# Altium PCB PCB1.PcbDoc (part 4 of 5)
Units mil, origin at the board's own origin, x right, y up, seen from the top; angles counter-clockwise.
Board outline 4463 x 4481 mil, 2 copper layers (Top Layer, Bottom Layer); 0 components, 111 nets, 310 pads, 0 vias.
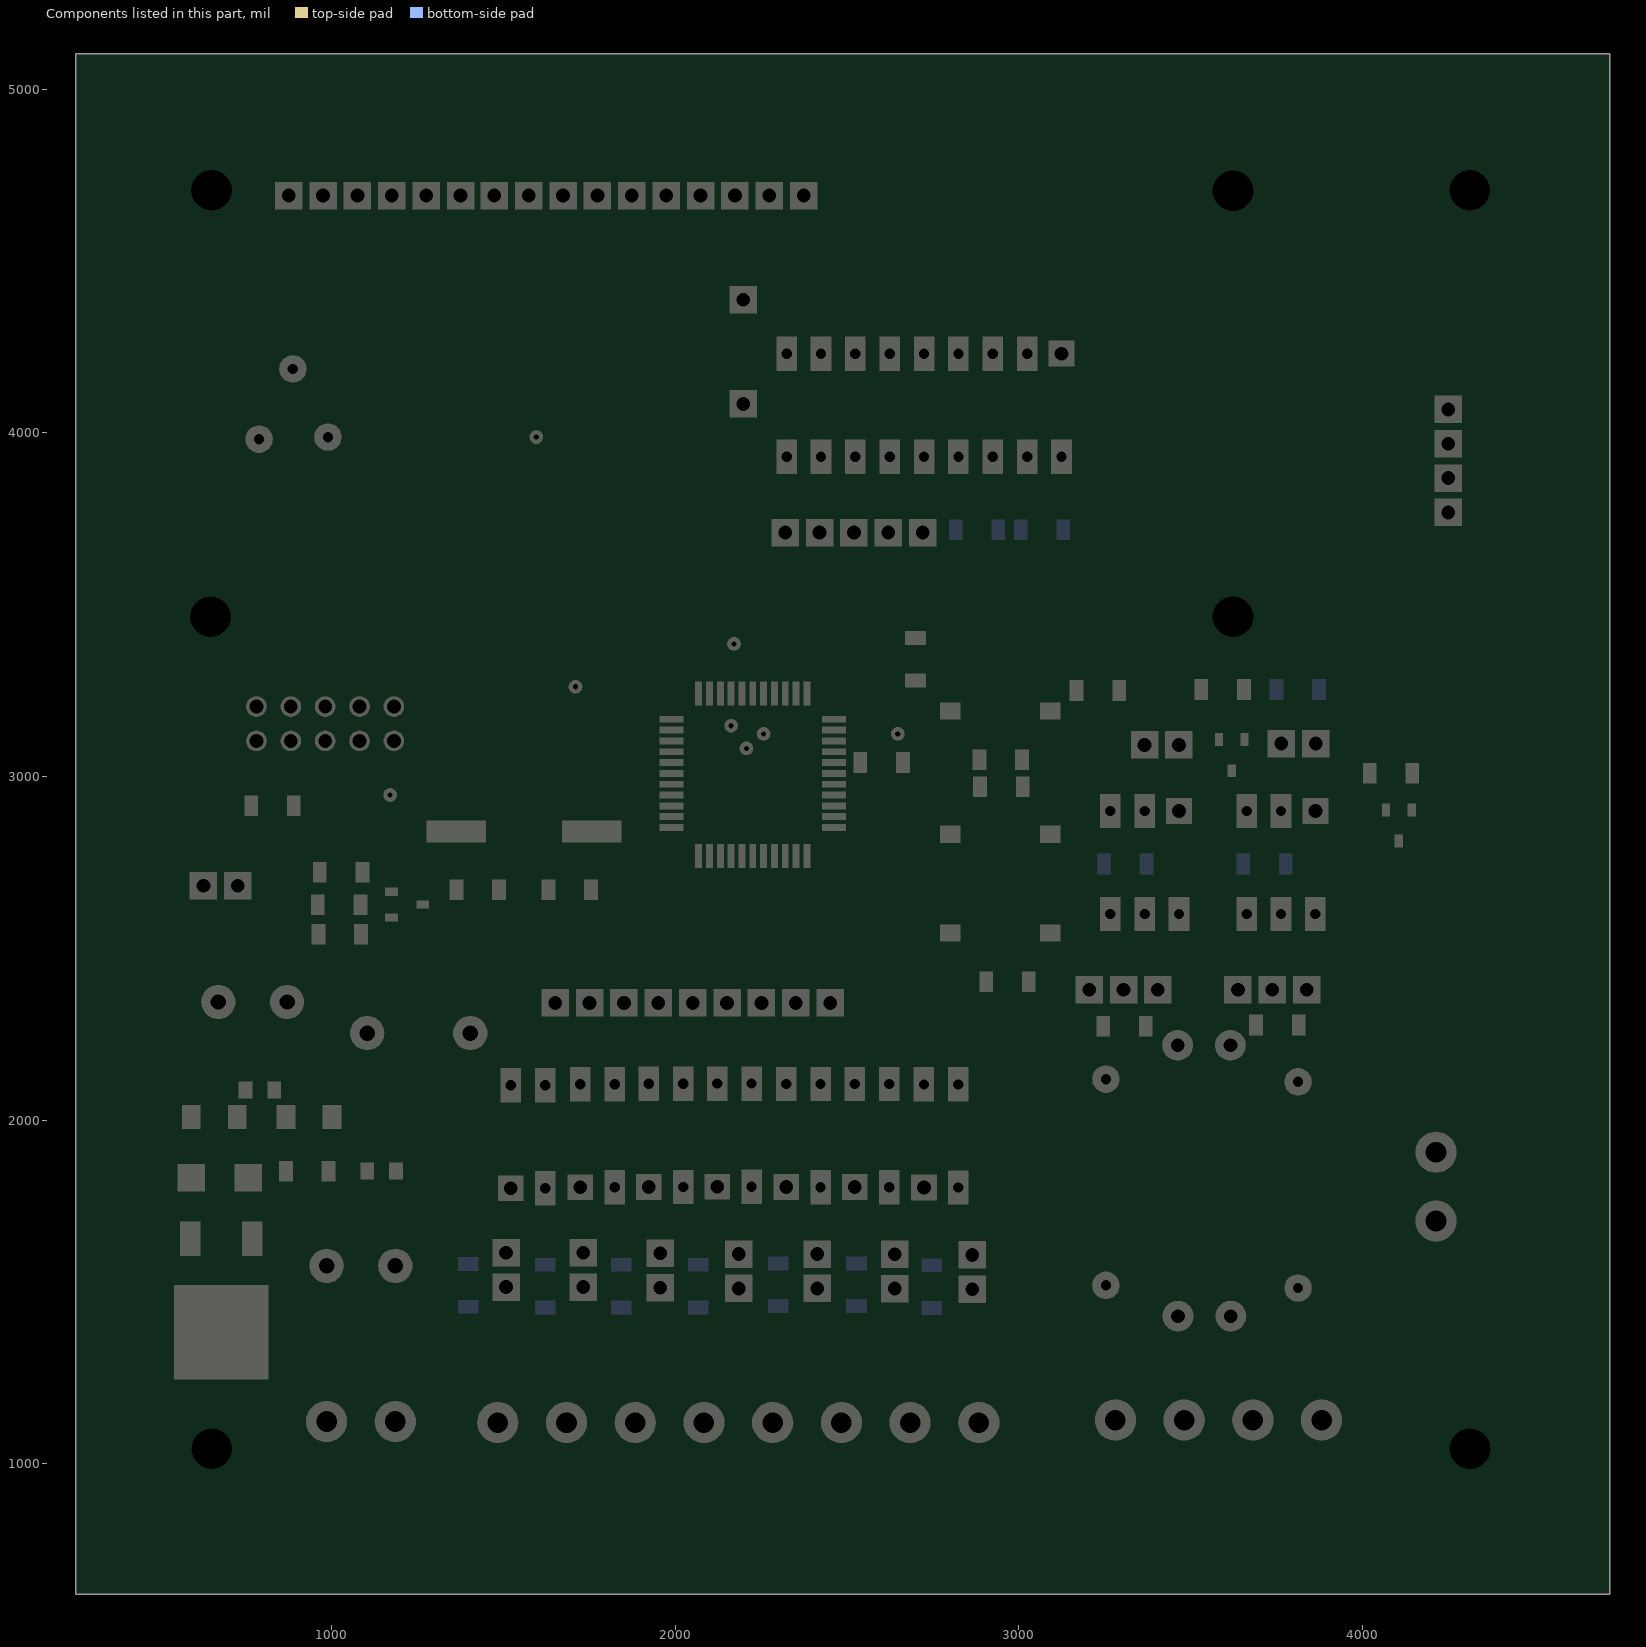
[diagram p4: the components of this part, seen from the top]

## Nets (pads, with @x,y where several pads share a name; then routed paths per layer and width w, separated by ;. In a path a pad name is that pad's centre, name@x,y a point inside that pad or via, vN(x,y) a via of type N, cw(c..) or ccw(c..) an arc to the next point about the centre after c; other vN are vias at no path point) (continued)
copper on no net: (continued)
  Bottom Layer w15: 514.04,931.9 4450.24,931.9 ; 514.04,956.9 588.64,956.9 ; 514.04,981.9 563.64,981.9 ; 514.04,1006.9 546.04,1006.9 ; 514.04,1031.9 546.04,1031.9 ; 514.04,1056.9 546.04,1056.9 ; 514.04,1081.9 546.04,1081.9 ; 514.04,1106.9 565.34,1106.9 ; 514.04,1131.9 590.34,1131.9 ; 514.04,1156.9 898.64,1156.9 ; 514.04,1181.9 921.24,1181.9 ; 514.04,1206.9 943.64,1206.9 ; 514.04,1231.9 943.64,1231.9 ; 514.04,1256.9 943.64,1256.9 ; 514.04,1281.9 943.64,1281.9 ; 514.04,1306.9 943.64,1306.9 ; 514.04,1331.9 943.64,1331.9 ; 514.04,1356.9 943.64,1356.9 ; 514.04,1381.9 943.64,1381.9 ; 514.04,1406.9 943.64,1406.9 ; 514.04,1431.9 943.64,1431.9 ; 514.04,1456.9 943.64,1456.9 ; 514.04,1481.9 943.64,1481.9 ; 514.04,1506.9 943.64,1506.9 ; 514.04,1531.9 920.44,1531.9 ; 514.04,1556.9 908.64,1556.9 ; 514.04,1581.9 908.64,1581.9 ; 514.04,1606.9 908.64,1606.9 ; 514.04,1631.9 932.64,1631.9 ; 514.04,1656.9 1363.34,1656.9 ; 514.04,1681.9 1363.34,1681.9 ; 514.04,1706.9 1363.34,1706.9 ; 514.04,1731.9 1363.34,1731.9 ; 514.04,1756.9 1363.34,1756.9 ; 514.04,1781.9 1367.54,1781.9 ; 514.04,1806.9 1392.54,1806.9 ; 514.04,1831.9 1417.54,1831.9 ; 514.04,1856.9 1457.34,1856.9 ; 514.04,1881.9 1766.84,1881.9 ; 514.04,1906.9 2934.54,1906.9 ; 514.04,1931.9 2934.54,1931.9 ; 514.04,1956.9 2934.54,1956.9 ; 514.04,1981.9 1626.64,1981.9 ; 514.04,2006.9 1601.64,2006.9 ; 514.04,2031.9 1464.84,2031.9 ; 514.04,2056.9 1464.84,2056.9 ; 514.04,2081.9 1464.84,2081.9 ; 514.04,2106.9 1464.84,2106.9 ; 514.04,2131.9 1464.84,2131.9 ; 514.04,2156.9 1464.84,2156.9 ; 514.04,2181.9 1065.74,2181.9 ; 514.04,2206.9 1040.74,2206.9 ; 514.04,2231.9 1026.74,2231.9 ; 514.04,2256.9 1026.74,2256.9 ; 514.04,2281.9 623.24,2281.9 ; 514.04,2306.9 598.24,2306.9 ; 514.04,2331.9 593.64,2331.9 ; 514.04,2356.9 593.64,2356.9 ; 514.04,2381.9 581.44,2381.9 ; 514.04,2406.9 581.44,2406.9 ; 514.04,2431.9 581.44,2431.9 ; 514.04,2456.9 581.44,2456.9 ; 514.04,2481.9 581.44,2481.9 ; 514.04,2506.9 581.44,2506.9 ; 514.04,2531.9 581.44,2531.9 ; 514.04,2556.9 581.44,2556.9 ; 514.04,2581.9 581.44,2581.9 ; 514.04,2606.9 581.44,2606.9 ; 514.04,2631.9 560.34,2631.9 ; 514.04,2656.9 560.34,2656.9 ; 514.04,2681.9 560.34,2681.9 ; 514.04,2706.9 560.34,2706.9 ; 514.04,2731.9 560.34,2731.9 ; 514.04,2756.9 592.84,2756.9 ; 514.04,2781.9 592.84,2781.9 ; 514.04,2806.9 592.84,2806.9 ; 514.04,2831.9 592.84,2831.9 ; 514.04,2856.9 592.84,2856.9 ; 514.04,2881.9 592.84,2881.9 ; 514.04,2906.9 592.84,2906.9 ; 514.04,2931.9 592.84,2931.9 ; 514.04,2956.9 592.84,2956.9 ; 514.04,2981.9 592.84,2981.9 ; 514.04,3006.9 592.84,3006.9 ; 514.04,3031.9 592.84,3031.9 ; 514.04,3056.9 592.84,3056.9 ; 514.04,3081.9 592.84,3081.9 ; 514.04,3106.9 592.84,3106.9 ; 514.04,3131.9 592.84,3131.9 ; 514.04,3156.9 616.24,3156.9 ; 514.04,3181.9 641.24,3181.9 ; 514.04,3206.9 724.74,3206.9 ; 514.04,3231.9 729.54,3231.9 ; 514.04,3256.9 754.54,3256.9 ; 514.04,3281.9 1096.44,3281.9 ; 514.04,3306.9 1096.44,3306.9 ; 514.04,3331.9 1096.44,3331.9 ; 514.04,3356.9 1096.44,3356.9 ; 514.04,3381.9 580.54,3381.9 ; 514.04,3406.9 555.54,3406.9 ; 514.04,3431.9 542.14,3431.9 ; 514.04,3456.9 542.14,3456.9 ; 514.04,3481.9 542.14,3481.9 ; 514.04,3506.9 542.14,3506.9 ; 514.04,3531.9 565.74,3531.9 ; 514.04,3556.9 590.74,3556.9 ; 514.04,3581.9 1241.64,3581.9 ; 514.04,3606.9 1241.64,3606.9 ; 514.04,3631.9 1241.64,3631.9 ; 514.04,3656.9 1241.64,3656.9 ; 514.04,3681.9 1241.64,3681.9 ; 514.04,3706.9 1241.64,3706.9 ; 514.04,3731.9 1241.64,3731.9 ; 514.04,3756.9 1241.64,3756.9 ; 514.04,3781.9 1241.64,3781.9 ; 514.04,3806.9 1241.64,3806.9 ; 514.04,3831.9 1241.64,3831.9 ; 514.04,3856.9 1241.64,3856.9 ; 514.04,3881.9 1241.64,3881.9 ; 514.04,3906.9 1241.64,3906.9 ; 514.04,3931.9 743.54,3931.9 ; 514.04,3956.9 722.14,3956.9 ; 514.04,3981.9 722.14,3981.9 ; 514.04,4006.9 722.14,4006.9 ; 514.04,4031.9 744.84,4031.9 ; 514.04,4056.9 754.64,4056.9 ; 514.04,4081.9 754.64,4081.9 ; 514.04,4106.9 754.64,4106.9 ; 514.04,4131.9 754.64,4131.9 ; 514.04,4156.9 754.64,4156.9 ; 514.04,4181.9 754.64,4181.9 ; 514.04,4206.9 754.64,4206.9 ; 514.04,4231.9 754.64,4231.9 ; 514.04,4256.9 754.64,4256.9 ; 514.04,4281.9 754.64,4281.9 ; 514.04,4306.9 754.64,4306.9 ; 514.04,4331.9 754.64,4331.9 ; 514.04,4356.9 754.64,4356.9 ; 514.04,4381.9 754.64,4381.9 ; 514.04,4406.9 754.64,4406.9 ; 514.04,4431.9 754.64,4431.9 ; 514.04,4456.9 759.14,4456.9 ; 514.04,4481.9 784.14,4481.9 ; 514.04,4506.9 809.14,4506.9 ; 514.04,4531.9 834.14,4531.9 ; 514.04,4556.9 836.94,4556.9 ; 514.04,4581.9 836.94,4581.9 ; 514.04,4606.9 600.04,4606.9 ; 514.04,4631.9 575.04,4631.9 ; 514.04,4656.9 550.04,4656.9 ; 514.04,4681.9 545.24,4681.9 ; 514.04,4706.9 545.24,4706.9 ; 514.04,4731.9 545.24,4731.9 ; 514.04,4756.9 552.44,4756.9 ; 514.04,4781.9 577.44,4781.9 ; 514.04,4806.9 602.44,4806.9 ; 514.04,4831.9 4450.24,4831.9 ; 539.04,906.9 539.04,4841.9 ; 564.04,906.9 564.04,981.5 ; 564.04,1105.6 564.04,2614.6 ; 564.04,2749.6 564.04,3398.4 ; 564.04,3530.2 564.04,4642.8 ; 564.04,4768.5 564.04,4841.9 ; 589.04,906.9 589.04,956.5 ; 589.04,1130.6 589.04,2365.6 ; 589.04,2749.6 589.04,3373.4 ; 589.04,3555.2 589.04,4617.8 ; 589.04,4793.5 589.04,4841.9 ; 614.04,906.9 614.04,937.3 ; 614.04,1149.8 614.04,2291.1 ; 614.04,3154.7 614.04,3358.1 ; 614.04,3570.6 614.04,4599.4 ; 614.04,4811.9 614.04,4841.9 ; 639.04,906.9 639.04,937.3 ; 639.04,1149.8 639.04,2266.1 ; 639.04,3179.7 639.04,3358.1 ; 639.04,3570.6 639.04,4599.4 ; 639.04,4811.9 639.04,4841.9 ; 662.84,2756.9 3172.74,2756.9 ; 662.84,2781.9 3200.34,2781.9 ; 662.84,2806.9 4450.24,2806.9 ; 662.84,2831.9 3208.84,2831.9 ; 662.84,2856.9 3208.84,2856.9 ; 662.84,2881.9 3208.84,2881.9 ; 662.84,2906.9 1142.94,2906.9 ; 662.84,2931.9 1123.64,2931.9 ; 662.84,2956.9 1123.64,2956.9 ; 662.84,2981.9 1140.14,2981.9 ; 662.84,3006.9 1182.74,3006.9 ; 662.84,3031.9 1207.74,3031.9 ; 662.84,3056.9 747.34,3056.9 ; 662.84,3081.9 724.74,3081.9 ; 664.04,906.9 664.04,937.3 ; 664.04,1149.8 664.04,2266.1 ; 664.04,2749.6 664.04,3105.7 ; 664.04,3189.5 664.04,3358.1 ; 664.04,3570.6 664.04,4599.4 ; 664.04,4811.9 664.04,4841.9 ; 665.24,3106.9 724.74,3106.9 ; 666.44,2431.9 3137.44,2431.9 ; 666.44,2456.9 3236.54,2456.9 ; 666.44,2481.9 3211.54,2481.9 ; 666.44,2506.9 3186.54,2506.9 ; 666.44,2531.9 3161.54,2531.9 ; 666.44,2556.9 3155.74,2556.9 ; 666.44,2581.9 3155.74,2581.9 ; 666.44,2606.9 3155.74,2606.9 ; 689.04,906.9 689.04,937.3 ; 689.04,1149.8 689.04,2266.1 ; 689.04,2421.1 689.04,2614.6 ; 689.04,2749.6 689.04,3119.5 ; 689.04,3189.5 689.04,3358.1 ; 689.04,3570.6 689.04,4599.4 ; 689.04,4811.9 689.04,4841.9 ; 700.54,4806.9 3575.94,4806.9 ; 702.94,4606.9 836.94,4606.9 ; 706.04,3556.9 1241.64,3556.9 ; 714.04,906.9 714.04,955.1 ; 714.04,1132.1 714.04,2276.9 ; 714.04,2410.3 714.04,2614.6 ; 714.04,2749.6 714.04,3119.5 ; 714.04,3189.5 714.04,3379.8 ; 714.04,3548.8 714.04,4618 ; 714.04,4793.3 714.04,4841.9 ; 714.24,1131.9 898.64,1131.9 ; 715.94,956.9 986.34,956.9 ; 716.14,3381.9 1120.04,3381.9 ; 717.44,2406.9 824.84,2406.9 ; 719.04,2281.9 823.24,2281.9 ; 725.54,4781.9 863.34,4781.9 ; 727.94,4631.9 808.44,4631.9 ; 731.04,3531.9 1241.64,3531.9 ; 739.04,906.9 739.04,980.1 ; 739.04,1107.1 739.04,2301.9 ; 739.04,2385.3 739.04,2614.6 ; 739.04,2749.6 739.04,3065.1 ; 739.04,3241.4 739.04,3404.8 ; 739.04,3523.8 739.04,3936.4 ; 739.04,4026.1 739.04,4643 ; 739.04,4768.3 739.04,4841.9 ; 739.24,1106.9 898.64,1106.9 ; 740.94,981.9 961.34,981.9 ; 741.14,3406.9 1145.04,3406.9 ; 742.44,2381.9 799.84,2381.9 ; 744.04,2306.9 798.24,2306.9 ; 748.64,2331.9 793.64,2331.9 ; 748.64,2356.9 793.64,2356.9 ; 750.54,4756.9 808.44,4756.9 ; 752.94,4656.9 808.44,4656.9 ; 754.54,3431.9 1170.04,3431.9 ; 754.54,3456.9 1195.04,3456.9 ; 754.54,3481.9 1220.04,3481.9 ; 754.54,3506.9 1241.64,3506.9 ; 757.74,4681.9 808.44,4681.9 ; 757.74,4706.9 808.44,4706.9 ; 757.74,4731.9 808.44,4731.9 ; 758.54,1006.9 942.44,1006.9 ; 758.54,1031.9 942.44,1031.9 ; 758.54,1056.9 928.54,1056.9 ; 758.54,1081.9 903.54,1081.9 ; 764.04,906.9 764.04,2614.6 ; 764.04,2749.6 764.04,3045.8 ; 764.04,3260.8 764.04,3913.7 ; 764.04,4461.8 764.04,4841.9 ; 789.04,906.9 789.04,2614.6 ; 789.04,2749.6 789.04,3045.8 ; 789.04,3260.8 789.04,3913.7 ; 789.04,4486.8 789.04,4841.9 ; 795.34,2631.9 3155.74,2631.9 ; 795.34,2656.9 3155.74,2656.9 ; 795.34,2681.9 3155.74,2681.9 ; 795.34,2706.9 3155.74,2706.9 ; 795.34,2731.9 3155.74,2731.9 ; 809.94,3256.9 854.44,3256.9 ; 814.04,906.9 814.04,2291.1 ; 814.04,2396.1 814.04,3053.8 ; 814.04,3252.7 814.04,3913.7 ; 814.04,4511.8 814.04,4622.4 ; 814.04,4757.4 814.04,4841.9 ; 817.14,3056.9 847.24,3056.9 ; 835.84,3931.9 949.94,3931.9 ; 839.04,906.9 839.04,2266.1 ; 839.04,3065.1 839.04,2421.1 ; 839.04,3241.5 839.04,3935.1 ; 839.04,4757.4 839.04,4841.9 ; 857.14,3956.9 924.94,3956.9 ; 857.14,3981.9 922.54,3981.9 ; 857.14,4006.9 920.84,4006.9 ; 864.04,906.9 864.04,2266.1 ; 864.04,2421.1 864.04,3045.8 ; 864.04,3260.8 864.04,4009.2 ; 864.04,4782.6 864.04,4841.9 ; 889.04,906.9 889.04,2266.1 ; 889.04,2421.1 889.04,3045.8 ; 889.04,3260.8 889.04,4009.2 ; 889.04,4803.7 889.04,4841.9 ; 909.94,3256.9 954.44,3256.9 ; 914.04,906.9 914.04,1071.4 ; 914.04,1174.7 914.04,1538.3 ; 914.04,1613.3 914.04,2276.9 ; 914.04,2410.3 914.04,3053.8 ; 914.04,3252.7 914.04,4009.2 ; 914.04,4803.7 914.04,4841.9 ; 917.14,3056.9 947.24,3056.9 ; 917.44,2406.9 1583.94,2406.9 ; 919.04,2281.9 1026.74,2281.9 ; 939.04,906.9 939.04,1046.4 ; 939.04,1199.7 939.04,1513.3 ; 939.04,1638.3 939.04,2301.9 ; 939.04,2385.3 939.04,3065.1 ; 939.04,3241.5 939.04,3942.7 ; 939.04,4803.7 939.04,4841.9 ; 942.44,2381.9 1583.94,2381.9 ; 944.04,2306.9 1048.54,2306.9 ; 948.64,2331.9 1583.94,2331.9 ; 948.64,2356.9 1583.94,2356.9 ; 964.04,906.9 964.04,979.2 ; 964.04,1653.3 964.04,3045.8 ; 964.04,3260.8 964.04,3919.7 ; 964.04,4803.7 964.04,4841.9 ; 989.04,906.9 989.04,955 ; 989.04,1653.3 989.04,3045.8 ; 989.04,3260.8 989.04,3919.7 ; 989.04,4803.7 989.04,4841.9 ; 1009.94,3256.9 1054.44,3256.9 ; 1014.04,906.9 1014.04,955 ; 1014.04,1653.3 1014.04,3053.8 ; 1014.04,3252.7 1014.04,3919.7 ; 1014.04,4803.7 1014.04,4841.9 ; 1017.14,3056.9 1047.24,3056.9 ; 1028.64,1206.9 1143.64,1206.9 ; 1028.64,1231.9 1143.64,1231.9 ; 1028.64,1256.9 1143.64,1256.9 ; 1028.64,1281.9 1143.64,1281.9 ; 1028.64,1306.9 1143.64,1306.9 ; 1028.64,1331.9 1143.64,1331.9 ; 1028.64,1356.9 1143.64,1356.9 ; 1028.64,1381.9 1143.64,1381.9 ; 1028.64,1406.9 1143.64,1406.9 ; 1028.64,1431.9 1143.64,1431.9 ; 1028.64,1456.9 1143.64,1456.9 ; 1028.64,1481.9 1143.64,1481.9 ; 1028.64,1506.9 1143.64,1506.9 ; 1030.24,3931.9 1241.64,3931.9 ; 1039.04,906.9 1039.04,955 ; 1039.04,1040 1039.04,1052.3 ; 1039.04,1193.9 1039.04,1519.1 ; 1039.04,1632.5 1039.04,2208.6 ; 1039.04,2297.4 1039.04,3065.1 ; 1039.04,3241.5 1039.04,3940.7 ; 1039.04,4803.7 1039.04,4841.9 ; 1039.64,1631.9 1132.64,1631.9 ; 1043.74,1056.9 1128.54,1056.9 ; 1051.04,1181.9 1121.24,1181.9 ; 1051.84,1531.9 1120.44,1531.9 ; 1063.64,1556.9 1108.64,1556.9 ; 1063.64,1581.9 1108.64,1581.9 ; 1063.64,1606.9 1108.64,1606.9 ; 1064.04,906.9 1064.04,955 ; 1064.04,1040 1064.04,1077.3 ; 1064.04,1168.9 1064.04,2183.6 ; 1064.04,2322.4 1064.04,3045.8 ; 1064.04,3260.8 1064.04,3952.2 ; 1064.04,4803.7 1064.04,4841.9 ; 1068.74,1081.9 1103.54,1081.9 ; 1073.64,1106.9 1098.64,1106.9 ; 1073.64,1131.9 1098.64,1131.9 ; 1073.64,1156.9 1098.64,1156.9 ; 1089.04,906.9 1089.04,955 ; 1089.04,1040 1089.04,2175.5 ; 1089.04,2330.5 1089.04,3045.8 ; 1089.04,3260.8 1089.04,3952.2 ; 1089.04,4803.7 1089.04,4841.9 ; 1114.04,906.9 1114.04,955 ; 1114.04,1040 1114.04,1071.4 ; 1114.04,1174.7 1114.04,1538.3 ; 1114.04,1613.3 1114.04,2175.5 ; 1114.04,2330.5 1114.04,3053.8 ; 1114.04,3375.9 1114.04,3952.2 ; 1114.04,4803.7 1114.04,4841.9 ; 1117.14,3056.9 1147.24,3056.9 ; 1139.04,906.9 1139.04,955 ; 1139.04,1040 1139.04,1046.4 ; 1139.04,1199.7 1139.04,1513.3 ; 1139.04,1638.3 1139.04,2178.2 ; 1139.04,2327.8 1139.04,2910.7 ; 1139.04,2980.8 1139.04,3065.1 ; 1139.04,3400.9 1139.04,3952.2 ; 1139.04,4803.7 1139.04,4841.9 ; 1142.74,2181.9 1365.74,2181.9 ; 1159.94,2306.9 1348.54,2306.9 ; 1164.04,906.9 1164.04,955 ; 1164.04,1653.3 1164.04,2203.2 ; 1164.04,2302.8 1164.04,2898.3 ; 1164.04,2993.3 1164.04,3045.8 ; 1164.04,3425.9 1164.04,3952.2 ; 1164.04,4803.7 1164.04,4841.9 ; 1167.74,2206.9 1340.74,2206.9 ; 1181.74,2231.9 1326.74,2231.9 ; 1181.74,2256.9 1326.74,2256.9 ; 1181.74,2281.9 1326.74,2281.9 ; 1189.04,906.9 1189.04,955 ; 1189.04,1653.3 1189.04,2898.3 ; 1189.04,3013.2 1189.04,3045.8 ; 1189.04,3450.9 1189.04,3952.2 ; 1189.04,4803.7 1189.04,4841.9 ; 1199.44,2906.9 3208.84,2906.9 ; 1214.04,906.9 1214.04,955 ; 1214.04,1653.3 1214.04,2921.5 ; 1214.04,3035.9 1214.04,3053.8 ; 1214.04,3152.7 1214.04,3153.8 ; 1214.04,3475.9 1214.04,3952.2 ; 1214.04,4803.7 1214.04,4841.9 ; 1217.14,3056.9 1539.84,3056.9 ; 1217.14,3156.9 1639.84,3156.9 ; 1217.14,3256.9 1663.04,3256.9 ; 1217.14,3281.9 1664.44,3281.9 ; 1218.64,2931.9 3208.84,2931.9 ; 1222.74,3306.9 1689.44,3306.9 ; 1228.64,1206.9 1447.44,1206.9 ; 1228.64,1231.9 1522.74,1231.9 ; 1228.64,1256.9 1497.74,1256.9 ; 1228.64,1281.9 1472.74,1281.9 ; 1228.64,1306.9 1447.74,1306.9 ; 1228.64,1331.9 1422.74,1331.9 ; 1228.64,1356.9 1397.74,1356.9 ; 1228.64,1381.9 1372.74,1381.9 ; 1228.64,1406.9 1364.94,1406.9 ; 1228.64,1431.9 1340.84,1431.9 ; 1228.64,1456.9 1340.84,1456.9 ; 1228.64,1481.9 1230.54,1481.9 ; 1231.74,2956.9 3208.84,2956.9 ; 1234.84,3231.9 1672.24,3231.9 ; 1234.94,3131.9 1614.84,3131.9 ; 1239.04,906.9 1239.04,955 ; 1239.04,1040 1239.04,1052.3 ; 1239.04,1193.9 1239.04,1479 ; 1239.04,1632.5 1239.04,2964.2 ; 1239.04,3035.9 1239.04,3078.8 ; 1239.04,3127.7 1239.04,3178.8 ; 1239.04,3227.7 1239.04,3316.3 ; 1239.04,3500.9 1239.04,3952.2 ; 1239.04,4803.7 1239.04,4841.9 ; 1239.64,1631.9 1363.34,1631.9 ; 1239.64,3081.9 1564.84,3081.9 ; 1239.64,3106.9 1589.84,3106.9 ; 1239.64,3181.9 1664.84,3181.9 ; 1239.64,3206.9 2819.64,3206.9 ; 1243.74,1056.9 1423.44,1056.9 ; 1251.04,1181.9 1422.44,1181.9 ; 1263.64,1556.9 1340.84,1556.9 ; 1263.64,1581.9 1340.84,1581.9 ; 1263.64,1606.9 1340.84,1606.9 ; 1264.04,906.9 1264.04,955 ; 1264.04,1040 1264.04,1077.3 ; 1264.04,1168.9 1264.04,1479 ; 1264.04,1549 1264.04,2965.9 ; 1264.04,3035.9 1264.04,3316.3 ; 1264.04,4803.7 1264.04,4841.9 ; 1268.74,1081.9 1398.44,1081.9 ; 1273.64,1106.9 1396.64,1106.9 ; 1273.64,1131.9 1396.64,1131.9 ; 1273.64,1156.9 1397.44,1156.9 ; 1289.04,906.9 1289.04,955 ; 1289.04,1040 1289.04,1479 ; 1289.04,1549 1289.04,2965.9 ; 1289.04,3035.9 1289.04,3316.3 ; 1289.04,4783 1289.04,4841.9 ; 1290.14,4781.9 3550.94,4781.9 ; 1314.04,906.9 1314.04,955 ; 1314.04,1040 1314.04,1479 ; 1314.04,1549 1314.04,2965.9 ; 1314.04,3035.9 1314.04,3316.3 ; 1314.04,4757.4 1314.04,4841.9 ; 1339.04,906.9 1339.04,955 ; 1339.04,1040 1339.04,1479 ; 1339.04,1549 1339.04,2208.6 ; 1339.04,2297.4 1339.04,2965.9 ; 1339.04,3035.9 1339.04,3316.3 ; 1339.04,4757.4 1339.04,4841.9 ; 1364.04,906.9 1364.04,955 ; 1364.04,1040 1364.04,1409.5 ; 1364.04,1778.4 1364.04,2183.6 ; 1364.04,2322.4 1364.04,2965.9 ; 1364.04,3035.9 1364.04,3316.3 ; 1364.04,4757.4 1364.04,4841.9 ; 1389.04,906.9 1389.04,955 ; 1389.04,1040 1389.04,1365.6 ; 1389.04,1803.4 1389.04,2175.5 ; 1389.04,2330.5 1389.04,2965.9 ; 1389.04,3035.9 1389.04,3316.3 ; 1389.04,4757.4 1389.04,4841.9 ; 1414.04,906.9 1414.04,955 ; 1414.04,1040 1414.04,1066.3 ; 1414.04,1173.6 1414.04,1340.6 ; 1414.04,1828.4 1414.04,2175.5 ; 1414.04,2330.5 1414.04,2965.9 ; 1414.04,3035.9 1414.04,3316.3 ; 1414.04,4757.4 1414.04,4841.9 ; 1439.04,906.9 1439.04,955 ; 1439.04,1198.6 1439.04,1315.6 ; 1439.04,1836.4 1439.04,2178.2 ; 1439.04,2327.8 1439.04,2965.9 ; 1439.04,3035.9 1439.04,3316.3 ; 1439.04,4757.4 1439.04,4841.9 ; 1442.74,2181.9 1489.34,2181.9 ; 1446.74,1406.9 1587.74,1406.9 ; 1455.84,1431.9 1565.24,1431.9 ; 1459.94,2306.9 1583.94,2306.9 ; 1463.94,956.9 4249.54,956.9 ; 1464.04,906.9 1464.04,957.1 ; 1464.04,1207.4 1464.04,1290.6 ; 1464.04,1389.6 1464.04,1446.5 ; 1464.04,1866.4 1464.04,2203.2 ; 1464.04,2302.8 1464.04,2965.9 ; 1464.04,3035.9 1464.04,3316.3 ; 1464.04,4757.4 1464.04,4841.9 ; 1467.74,2206.9 1489.34,2206.9 ; 1471.74,1381.9 1587.74,1381.9 ; 1481.74,2231.9 1489.34,2231.9 ; 1481.74,2256.9 1504.74,2256.9 ; 1481.74,2281.9 1529.74,2281.9 ; 1488.94,981.9 4224.54,981.9 ; 1489.04,906.9 1489.04,982.1 ; 1489.04,1207.4 1489.04,1265.6 ; 1489.04,1364.6 1489.04,1446.5 ; 1489.04,1866.4 1489.04,2023.9 ; 1489.04,2178.9 1489.04,2965.9 ; 1489.04,3035.9 1489.04,3316.3 ; 1489.04,4757.4 1489.04,4841.9 ; 1496.74,1356.9 1598.44,1356.9 ; 1513.94,1006.9 4206.94,1006.9 ; 1514.04,906.9 1514.04,1007.1 ; 1514.04,1207.4 1514.04,1240.6 ; 1514.04,1339.6 1514.04,1446.5 ; 1514.04,1866.4 1514.04,2023.9 ; 1514.04,2266.3 1514.04,2965.9 ; 1514.04,3035.9 1514.04,3316.3 ; 1514.04,4757.4 1514.04,4841.9 ; 1520.94,1206.9 1547.74,1206.9 ; 1521.74,1331.9 1623.44,1331.9 ; 1526.64,1031.9 4206.94,1031.9 ; 1539.04,906.9 1539.04,1051.1 ; 1539.04,1188.8 1539.04,1215.6 ; 1539.04,1314.6 1539.04,1446.5 ; 1539.04,1866.4 1539.04,2023.9 ; 1539.04,2291.3 1539.04,2965.9 ; 1539.04,3056.1 1539.04,3316.3 ; 1539.04,4757.4 1539.04,4841.9 ; 1544.84,1056.9 1623.44,1056.9 ; 1545.94,1181.9 1572.74,1181.9 ; 1546.74,1306.9 1648.44,1306.9 ; 1563.84,2981.9 3431.34,2981.9 ; 1564.04,906.9 1564.04,1076.1 ; 1564.04,1163.8 1564.04,1190.6 ; 1564.04,1289.6 1564.04,1446.5 ; 1564.04,1866.4 1564.04,2023.9 ; 1564.04,2295.1 1564.04,2982.1 ; 1564.04,3081.1 1564.04,3316.3 ; 1564.04,4757.4 1564.04,4841.9 ; 1569.84,1081.9 1598.44,1081.9 ; 1570.94,1156.9 1597.34,1156.9 ; 1571.64,1106.9 1596.64,1106.9 ; 1571.64,1131.9 1596.64,1131.9 ; 1571.74,1281.9 1673.44,1281.9 ; 1588.84,3006.9 3431.34,3006.9 ; 1589.04,906.9 1589.04,1165.6 ; 1589.04,1264.6 1589.04,1366.3 ; 1589.04,1878.9 1589.04,2019.5 ; 1589.04,2408.3 1589.04,3007.1 ; 1589.04,3106.1 1589.04,3316.3 ; 1589.04,4757.4 1589.04,4841.9 ; 1596.74,1256.9 1698.44,1256.9 ; 1613.84,3031.9 3298.84,3031.9 ; 1614.04,906.9 1614.04,1066.3 ; 1614.04,1239.6 1614.04,1341.3 ; 1614.04,1878.9 1614.04,1994.5 ; 1614.04,2408.3 1614.04,3032.1 ; 1614.04,3131.1 1614.04,3316.3 ; 1614.04,4757.4 1614.04,4841.9 ; 1621.74,1231.9 1723.44,1231.9 ; 1638.84,3056.9 2165.34,3056.9 ; 1639.04,906.9 1639.04,1041.3 ; 1639.04,1214.6 1639.04,1316.3 ; 1639.04,1878.9 1639.04,1975.5 ; 1639.04,2408.3 1639.04,3057.1 ; 1639.04,3156.1 1639.04,3316.3 ; 1639.04,4757.4 1639.04,4841.9 ; 1646.74,1206.9 1647.44,1206.9 ; 1657.74,1406.9 1808.64,1406.9 ; 1663.84,3081.9 2160.24,3081.9 ; 1664.04,906.9 1664.04,1032.4 ; 1664.04,1207.4 1664.04,1291.3 ; 1664.04,1390.3 1664.04,1407.5 ; 1664.04,1878.9 1664.04,1975.5 ; 1664.04,2408.3 1664.04,3082.1 ; 1664.04,3181.1 1664.04,3240.1 ; 1664.04,3281.5 1664.04,3316.3 ; 1664.04,4757.4 1664.04,4841.9 ; 1672.44,1381.9 1808.64,1381.9 ; 1680.24,1431.9 1785.74,1431.9 ; 1688.84,3106.9 2136.64,3106.9 ; 1689.04,906.9 1689.04,1032.4 ; 1689.04,1207.4 1689.04,1266.3 ; 1689.04,1365.3 1689.04,1446.5 ; 1689.04,1869.6 1689.04,1975.5 ; 1689.04,2408.3 1689.04,3107.1 ; 1689.04,3182.4 1689.04,3215.1 ; 1689.04,3306.5 1689.04,3316.3 ; 1689.04,4757.4 1689.04,4841.9 ; 1697.44,1356.9 1808.64,1356.9 ; 1714.04,906.9 1714.04,1032.4 ; 1714.04,1207.4 1714.04,1241.3 ; 1714.04,1340.3 1714.04,1446.5 ; 1714.04,1869.6 1714.04,1975.5 ; 1714.04,2408.3 1714.04,3112.4 ; 1714.04,3182.4 1714.04,3213.3 ; 1714.04,3313.7 1714.04,3316.3 ; 1714.04,4757.4 1714.04,4841.9 ; 1720.94,1206.9 1748.44,1206.9 ; 1722.44,1331.9 1822.74,1331.9 ; 1739.04,906.9 1739.04,1051.1 ; 1739.04,1188.8 1739.04,1216.3 ; 1739.04,1315.3 1739.04,1446.5 ; 1739.04,1869.6 1739.04,1975.5 ; 1739.04,2408.3 1739.04,3112.4 ; 1739.04,3182.4 1739.04,3222.1 ; 1739.04,4757.4 1739.04,4841.9 ; 1744.94,1056.9 1823.44,1056.9 ; 1745.94,1181.9 1773.44,1181.9 ; 1747.44,1306.9 1847.74,1306.9 ; 1748.84,3231.9 2844.64,3231.9 ; 1758.04,3256.9 2869.64,3256.9 ; 1764.04,906.9 1764.04,1076.1 ; 1764.04,1163.8 1764.04,1191.3 ; 1764.04,1290.3 1764.04,1446.5 ; 1764.04,1869.6 1764.04,1975.5 ; 1764.04,2408.3 1764.04,3112.4 ; 1764.04,3182.4 1764.04,3264.8 ; 1764.04,4757.4 1764.04,4841.9 ; 1769.94,1081.9 1798.44,1081.9 ; 1770.94,1156.9 1797.44,1156.9 ; 1771.64,1106.9 1796.64,1106.9 ; 1771.64,1131.9 1796.64,1131.9 ; 1772.44,1281.9 1872.74,1281.9 ; 1781.14,3281.9 2894.64,3281.9 ; 1789.04,906.9 1789.04,1166.3 ; 1789.04,1265.3 1789.04,1407.5 ; 1789.04,1882.1 1789.04,1975.5 ; 1789.04,2408.3 1789.04,3112.4 ; 1789.04,3182.4 1789.04,3289.8 ; 1789.04,4757.4 1789.04,4841.9 ; 1797.44,1256.9 1897.74,1256.9 ; 1806.14,3306.9 2919.64,3306.9 ; 1814.04,906.9 1814.04,1066.3 ; 1814.04,1240.3 1814.04,1340.6 ; 1814.04,1882.1 1814.04,1975.5 ; 1814.04,2408.3 1814.04,3112.4 ; 1814.04,3182.4 1814.04,3314.8 ; 1814.04,4757.4 1814.04,4841.9 ; 1822.04,1981.9 1823.44,1981.9 ; 1822.44,1231.9 1922.74,1231.9 ; 1828.24,3431.9 2150.64,3431.9 ; 1828.24,3456.9 3069.64,3456.9 ; 1828.24,3481.9 3094.64,3481.9 ; 1828.24,3506.9 3094.74,3506.9 ; 1828.24,3531.9 3094.74,3531.9 ; 1828.24,3556.9 3094.74,3556.9 ; 1828.24,3581.9 3094.74,3581.9 ; 1828.24,3606.9 2700.64,3606.9 ; 1828.24,3631.9 2683.34,3631.9 ; 1828.24,3656.9 2253.24,3656.9 ; 1828.24,3681.9 2253.24,3681.9 ; 1828.24,3706.9 2253.24,3706.9 ; 1828.24,3731.9 2253.24,3731.9 ; 1828.24,3756.9 2253.24,3756.9 ; 1828.24,3781.9 2285.74,3781.9 ; 1828.24,3806.9 2285.74,3806.9 ; 1828.24,3831.9 2285.74,3831.9 ; 1828.24,3856.9 2267.24,3856.9 ; 1828.24,3881.9 2267.24,3881.9 ; 1828.24,3906.9 2267.24,3906.9 ; 1828.24,3931.9 2267.24,3931.9 ; 1828.24,3956.9 2267.24,3956.9 ; 1828.24,3981.9 2267.24,3981.9 ; 1828.24,4006.9 2267.24,4006.9 ; 1828.24,4031.9 2131.24,4031.9 ; 1828.24,4056.9 2131.24,4056.9 ; 1828.24,4081.9 2131.24,4081.9 ; 1828.24,4106.9 2131.24,4106.9 ; 1828.24,4131.9 2131.24,4131.9 ; 1828.24,4156.9 2267.24,4156.9 ; 1828.24,4181.9 2267.24,4181.9 ; 1828.24,4206.9 2211.84,4206.9 ; 1828.24,4231.9 2186.84,4231.9 ; 1828.24,4256.9 2163.74,4256.9 ; 1828.24,4281.9 2163.74,4281.9 ; 1828.24,4306.9 2163.74,4306.9 ; 1828.24,4331.9 2131.24,4331.9 ; 1828.24,4356.9 2131.24,4356.9 ; 1831.14,3331.9 2944.64,3331.9 ; 1837.84,4381.9 2131.24,4381.9 ; 1839.04,906.9 1839.04,1041.3 ; 1839.04,1215.3 1839.04,1315.6 ; 1839.04,1882.1 1839.04,1974.7 ; 1839.04,2408.3 1839.04,3112.4 ; 1839.04,3182.4 1839.04,3339.8 ; 1839.04,3420.6 1839.04,4383.1 ; 1839.04,4757.4 1839.04,4841.9 ; 1862.84,4406.9 2131.24,4406.9 ; 1864.04,906.9 1864.04,1032.4 ; 1864.04,1207.4 1864.04,1290.6 ; 1864.04,1882.1 1864.04,1974.7 ; 1864.04,2408.3 1864.04,3112.4 ; 1864.04,3182.4 1864.04,3350.6 ; 1864.04,3420.6 1864.04,4408.1 ; 1864.04,4757.4 1864.04,4841.9 ; 1878.64,1381.9 2031.84,1381.9 ; 1878.64,1406.9 2031.84,1406.9 ; 1881.84,1881.9 1966.04,1881.9 ; 1887.84,4431.9 2131.24,4431.9 ; 1889.04,906.9 1889.04,1032.4 ; 1889.04,1207.4 1889.04,1265.6 ; 1889.04,1364.6 1889.04,1407.5 ; 1889.04,1870.4 1889.04,1974.7 ; 1889.04,2408.3 1889.04,3112.4 ; 1889.04,3182.4 1889.04,3350.6 ; 1889.04,3420.6 1889.04,4433.1 ; 1889.04,4757.4 1889.04,4841.9 ; 1896.74,1356.9 2031.84,1356.9 ; 1900.74,1431.9 2010.14,1431.9 ; 1909.34,4456.9 4450.24,4456.9 ; 1909.34,4481.9 4450.24,4481.9 ; 1909.34,4506.9 4450.24,4506.9 ; 1909.34,4531.9 4450.24,4531.9 ; 1909.34,4556.9 4450.24,4556.9 ; 1909.34,4581.9 4450.24,4581.9 ; 1909.34,4606.9 3570.34,4606.9 ; 1914.04,906.9 1914.04,1032.4 ; 1914.04,1207.4 1914.04,1240.6 ; 1914.04,1339.6 1914.04,1445 ; 1914.04,1870.4 1914.04,1974.7 ; 1914.04,2408.3 1914.04,3112.4 ; 1914.04,3182.4 1914.04,3350.6 ; 1914.04,3420.6 1914.04,4622.4 ; 1914.04,4757.4 1914.04,4841.9 ; 1920.94,1206.9 1947.74,1206.9 ; 1921.74,1331.9 2031.84,1331.9 ; 1939.04,906.9 1939.04,1051.1 ; 1939.04,1188.8 1939.04,1215.6 ; 1939.04,1314.6 1939.04,1445 ; 1939.04,1870.4 1939.04,1974.7 ; 1939.04,2408.3 1939.04,3112.4 ; 1939.04,3182.4 1939.04,3350.6 ; 1939.04,3420.6 1939.04,4622.4 ; 1939.04,4757.4 1939.04,4841.9 ; 1944.94,1056.9 2023.44,1056.9 ; 1945.94,1181.9 1972.74,1181.9 ; 1946.74,1306.9 2047.74,1306.9 ; 1964.04,906.9 1964.04,1076.1 ; 1964.04,1163.8 1964.04,1190.6 ; 1964.04,1289.6 1964.04,1445 ; 1964.04,1870.4 1964.04,1974.7 ; 1964.04,2408.3 1964.04,3112.4 ; 1964.04,3182.4 1964.04,3350.6 ; 1964.04,3420.6 1964.04,4622.4 ; 1964.04,4757.4 1964.04,4841.9 ; 1969.94,1081.9 1998.44,1081.9 ; 1970.94,1156.9 1997.34,1156.9 ; 1971.64,1106.9 1996.64,1106.9 ; 1971.64,1131.9 1996.64,1131.9 ; 1971.74,1281.9 2072.74,1281.9 ; 1989.04,906.9 1989.04,1165.6 ; 1989.04,1264.6 1989.04,1445 ; 1989.04,1882.9 1989.04,1974.7 ; 1989.04,2408.3 1989.04,3112.4 ; 1989.04,3182.4 1989.04,3350.6 ; 1989.04,3420.6 1989.04,4622.4 ; 1989.04,4757.4 1989.04,4841.9 ; 1996.74,1256.9 2097.74,1256.9 ; 2014.04,906.9 2014.04,1066.3 ; 2014.04,1239.6 2014.04,1407.5 ; 2014.04,1882.9 2014.04,1974.7 ; 2014.04,2408.3 2014.04,3112.4 ; 2014.04,3182.4 2014.04,3350.6 ; 2014.04,3420.6 2014.04,4622.4 ; 2014.04,4757.4 2014.04,4841.9 ; 2021.74,1231.9 2122.74,1231.9 ; 2039.04,906.9 2039.04,1041.3 ; 2039.04,1214.6 2039.04,1315.6 ; 2039.04,1882.9 2039.04,1972.7 ; 2039.04,2408.3 2039.04,3112.4 ; 2039.04,3182.4 2039.04,3350.6 ; 2039.04,3420.6 2039.04,4622.4 ; 2039.04,4757.4 2039.04,4841.9 ; 2046.74,1206.9 2047.44,1206.9 ; 2064.04,906.9 2064.04,1032.4 ; 2064.04,1207.4 2064.04,1290.6 ; 2064.04,1882.9 2064.04,1972.7 ; 2064.04,2408.3 2064.04,3112.4 ; 2064.04,3182.4 2064.04,3350.6 ; 2064.04,3420.6 2064.04,4622.4 ; 2064.04,4757.4 2064.04,4841.9 ; 2081.04,1881.9 2165.24,1881.9 ; 2089.04,906.9 2089.04,1032.4 ; 2089.04,1207.4 2089.04,1265.6 ; 2089.04,1871.2 2089.04,1972.7 ; 2089.04,2408.3 2089.04,3112.4 ; 2089.04,3182.4 2089.04,3350.6 ; 2089.04,3420.6 2089.04,4622.4 ; 2089.04,4757.4 2089.04,4841.9 ; 2101.84,1356.9 2264.94,1356.9 ; 2101.84,1381.9 2264.94,1381.9 ; 2101.84,1406.9 2264.94,1406.9 ; 2114.04,906.9 2114.04,1032.4 ; 2114.04,1207.4 2114.04,1240.6 ; 2114.04,1339.6 2114.04,1407.5 ; 2114.04,1871.2 2114.04,1972.7 ; 2114.04,2408.3 2114.04,3112.4 ; 2114.04,3182.4 2114.04,3350.6 ; 2114.04,3420.6 2114.04,4622.4 ; 2114.04,4757.4 2114.04,4841.9 ; 2120.94,1206.9 2147.74,1206.9 ; 2121.74,1331.9 2264.94,1331.9 ; 2125.14,1431.9 2242.44,1431.9 ; 2139.04,906.9 2139.04,1051.1 ; 2139.04,1188.8 2139.04,1215.6 ; 2139.04,1314.6 2139.04,1442.6 ; 2139.04,1871.2 2139.04,1972.7 ; 2139.04,2408.3 2139.04,3104.5 ; 2139.04,3190.3 2139.04,3350.6 ; 2139.04,3420.6 2139.04,4016.1 ; 2139.04,4151.1 2139.04,4319.3 ; 2139.04,4454.3 2139.04,4622.4 ; 2139.04,4757.4 2139.04,4841.9 ; 2144.94,1056.9 2223.44,1056.9 ; 2145.94,1181.9 2172.74,1181.9 ; 2146.74,1306.9 2264.94,1306.9 ; 2164.04,906.9 2164.04,1076.1 ; 2164.04,1163.8 2164.04,1190.6 ; 2164.04,1289.6 2164.04,1442.6 ; 2164.04,1871.2 2164.04,1972.7 ; 2164.04,2408.3 2164.04,3058.2 ; 2164.04,3194.9 2164.04,3338.1 ; 2164.04,3433.1 2164.04,4016.1 ; 2164.04,4151.1 2164.04,4254.6 ; 2164.04,4454.3 2164.04,4622.4 ; 2164.04,4757.4 2164.04,4841.9 ; 2169.94,1081.9 2198.44,1081.9 ; 2170.94,1156.9 2197.34,1156.9 ; 2171.64,1106.9 2196.64,1106.9 ; 2171.64,1131.9 2196.64,1131.9 ; 2171.74,1281.9 2272.74,1281.9 ; 2189.04,906.9 2189.04,1165.6 ; 2189.04,1264.6 2189.04,1442.6 ; 2189.04,1883.7 2189.04,1972.7 ; 2189.04,2408.3 2189.04,3034.1 ; 2189.04,3188.8 2189.04,3338.1 ; 2189.04,3433.1 2189.04,4016.1 ; 2189.04,4151.1 2189.04,4229.6 ; 2189.04,4454.3 2189.04,4622.4 ; 2189.04,4757.4 2189.04,4841.9 ; 2192.44,3431.9 3044.64,3431.9 ; 2196.04,3181.9 2794.64,3181.9 ; 2196.74,1256.9 2297.74,1256.9 ; 2210.04,3356.9 2969.64,3356.9 ; 2210.84,3156.9 2223.74,3156.9 ; 2214.04,906.9 2214.04,1066.3 ; 2214.04,1239.6 2214.04,1442.6 ; 2214.04,1883.7 2214.04,1972.7 ; 2214.04,2408.3 2214.04,3034.1 ; 2214.04,3147.2 2214.04,3360.9 ; 2214.04,3410.3 2214.04,4016.1 ; 2214.04,4151.1 2214.04,4204.6 ; 2214.04,4454.3 2214.04,4622.4 ; 2214.04,4757.4 2214.04,4841.9 ; 2217.44,3406.9 3019.64,3406.9 ; 2219.04,3381.9 2994.64,3381.9 ; 2221.74,1231.9 2322.74,1231.9 ; 2233.74,4306.9 2267.24,4306.9 ; 2235.84,4281.9 2267.24,4281.9 ; 2239.04,906.9 2239.04,1041.3 ; 2239.04,1214.6 2239.04,1442.6 ; 2239.04,1883.7 2239.04,1969 ; 2239.04,2408.3 2239.04,3045.7 ; 2239.04,3171.3 2239.04,4016.1 ; 2239.04,4151.1 2239.04,4195.1 ; 2239.04,4278.6 2239.04,4319.3 ; 2239.04,4454.3 2239.04,4622.4 ; 2239.04,4757.4 2239.04,4841.9 ; 2246.74,1206.9 2247.44,1206.9 ; 2264.04,906.9 2264.04,1032.4 ; 2264.04,1207.4 2264.04,1411.4 ; 2264.04,1883.7 2264.04,1969 ; 2264.04,2408.3 2264.04,3046.6 ; 2264.04,3171.3 2264.04,3642.1 ; 2264.04,3777.1 2264.04,4016.1 ; 2264.04,4151.1 2264.04,4195.1 ; 2264.04,4265.1 2264.04,4319.3 ; 2264.04,4454.3 2264.04,4622.4 ; 2264.04,4757.4 2264.04,4841.9 ; 2280.24,1881.9 2366.04,1881.9 ; 2289.04,906.9 2289.04,1032.4 ; 2289.04,1207.4 2289.04,1265.6 ; 2289.04,1870 2289.04,1969 ; 2289.04,2408.3 2289.04,3046.6 ; 2289.04,3159.7 2289.04,3642.1 ; 2289.04,4007.6 2289.04,4026.1 ; 2289.04,4141.1 2289.04,4152.6 ; 2289.04,4307.6 2289.04,4329.3 ; 2289.04,4444.3 2289.04,4622.4 ; 2289.04,4757.4 2289.04,4841.9 ; 2314.04,906.9 2314.04,1032.4 ; 2314.04,1207.4 2314.04,1240.6 ; 2314.04,1870 2314.04,1969 ; 2314.04,2408.3 2314.04,3046.6 ; 2314.04,3158.8 2314.04,3642.1 ; 2314.04,4007.6 2314.04,4026.1 ; 2314.04,4141.1 2314.04,4152.6 ; 2314.04,4307.6 2314.04,4329.3 ; 2314.04,4444.3 2314.04,4622.4 ; 2314.04,4757.4 2314.04,4841.9 ; 2320.94,1206.9 2347.74,1206.9 ; 2334.94,1331.9 2493.14,1331.9 ; 2334.94,1356.9 2493.14,1356.9 ; 2334.94,1381.9 2493.14,1381.9 ; 2334.94,1406.9 2493.14,1406.9 ; 2339.04,906.9 2339.04,1051.1 ; 2339.04,1188.8 2339.04,1215.6 ; 2339.04,1314.6 2339.04,1411.4 ; 2339.04,1870 2339.04,1969 ; 2339.04,2408.3 2339.04,3046.6 ; 2339.04,3158.8 2339.04,3642.1 ; 2339.04,4007.6 2339.04,4026.1 ; 2339.04,4141.1 2339.04,4152.6 ; 2339.04,4307.6 2339.04,4329.3 ; 2339.04,4444.3 2339.04,4622.4 ; 2339.04,4757.4 2339.04,4841.9 ; 2344.94,1056.9 2423.44,1056.9 ; 2345.94,1181.9 2372.74,1181.9 ; 2346.74,1306.9 2493.14,1306.9 ; 2357.44,1431.9 2470.74,1431.9 ; 2364.04,906.9 2364.04,1076.1 ; 2364.04,1163.8 2364.04,1190.6 ; 2364.04,1289.6 2364.04,1442.6 ; 2364.04,1870 2364.04,1969 ; 2364.04,2408.3 2364.04,3046.6 ; 2364.04,3158.8 2364.04,3642.1 ; 2364.04,4007.6 2364.04,4026.1 ; 2364.04,4141.1 2364.04,4152.6 ; 2364.04,4307.6 2364.04,4329.3 ; 2364.04,4444.3 2364.04,4622.4 ; 2364.04,4757.4 2364.04,4841.9 ; 2369.94,1081.9 2398.44,1081.9 ; 2370.94,1156.9 2397.34,1156.9 ; 2371.64,1106.9 2396.64,1106.9 ; 2371.64,1131.9 2396.64,1131.9 ; 2371.74,1281.9 2493.14,1281.9 ; 2389.04,906.9 2389.04,1165.6 ; 2389.04,1264.6 2389.04,1442.6 ; 2389.04,1882.5 2389.04,1969 ; 2389.04,2408.3 2389.04,3046.6 ; 2389.04,3158.8 2389.04,3642.1 ; 2389.04,4007.6 2389.04,4026.1 ; 2389.04,4141.1 2389.04,4152.6 ; 2389.04,4307.6 2389.04,4329.3 ; 2389.04,4444.3 2389.04,4622.4 ; 2389.04,4757.4 2389.04,4841.9 ; 2396.74,1256.9 2497.54,1256.9 ; 2414.04,906.9 2414.04,1066.3 ; 2414.04,1239.6 2414.04,1442.6 ; 2414.04,1882.5 2414.04,1969 ; 2414.04,2269.1 2414.04,2273.3 ; 2414.04,2408.3 2414.04,3046.6 ; 2414.04,3158.8 2414.04,3642.1 ; 2414.04,4007.6 2414.04,4026.1 ; 2414.04,4141.1 2414.04,4152.6 ; 2414.04,4307.6 2414.04,4329.3 ; 2414.04,4444.3 2414.04,4622.4 ; 2414.04,4757.4 2414.04,4841.9 ; 2421.74,1231.9 2522.54,1231.9 ; 2439.04,906.9 2439.04,1041.3 ; 2439.04,1214.6 2439.04,1442.6 ; 2439.04,1882.5 2439.04,1970.9 ; 2439.04,2258.9 2439.04,2273.3 ; 2439.04,2408.3 2439.04,3046.6 ; 2439.04,3158.8 2439.04,3642.1 ; 2439.04,4007.6 2439.04,4026.1 ; 2439.04,4141.1 2439.04,4152.6 ; 2439.04,4307.6 2439.04,4329.3 ; 2439.04,4444.3 2439.04,4622.4 ; 2439.04,4757.4 2439.04,4841.9 ; 2441.84,4631.9 3545.34,4631.9 ; 2441.84,4656.9 3520.34,4656.9 ; 2441.84,4681.9 3517.14,4681.9 ; 2441.84,4706.9 3517.14,4706.9 ; 2441.84,4731.9 3517.14,4731.9 ; 2441.84,4756.9 3525.94,4756.9 ; 2446.74,1206.9 2447.44,1206.9 ; 2464.04,906.9 2464.04,1032.4 ; 2464.04,1207.4 2464.04,1442.6 ; 2464.04,1882.5 2464.04,1970.9 ; 2464.04,2258.9 2464.04,2273.3 ; 2464.04,2408.3 2464.04,3046.6 ; 2464.04,3158.8 2464.04,3642.1 ; 2464.04,4007.6 2464.04,4026.1 ; 2464.04,4141.1 2464.04,4152.6 ; 2464.04,4307.6 2464.04,4329.3 ; 2464.04,4444.3 2464.04,4841.9 ; 2481.04,1881.9 2565.54,1881.9 ; 2489.04,906.9 2489.04,1032.4 ; 2489.04,1207.4 2489.04,1411.4 ; 2489.04,1870 2489.04,1970.9 ; 2489.04,2258.9 2489.04,2273.3 ; 2489.04,2408.3 2489.04,3046.6 ; 2489.04,3158.8 2489.04,3642.1 ; 2489.04,4007.6 2489.04,4026.1 ; 2489.04,4141.1 2489.04,4152.6 ; 2489.04,4307.6 2489.04,4329.3 ; 2489.04,4444.3 2489.04,4841.9 ; 2514.04,906.9 2514.04,1032.4 ; 2514.04,1207.4 2514.04,1240.5 ; 2514.04,1870 2514.04,1970.9 ; 2514.04,2258.9 2514.04,2273.3 ; 2514.04,2408.3 2514.04,3046.6 ; 2514.04,3158.8 2514.04,3642.1 ; 2514.04,4007.6 2514.04,4026.1 ; 2514.04,4141.1 2514.04,4152.6 ; 2514.04,4307.6 2514.04,4329.3 ; 2514.04,4444.3 2514.04,4841.9 ; 2518.84,2281.9 3162.44,2281.9 ; 2518.84,2306.9 3162.44,2306.9 ; 2518.84,2331.9 3137.44,2331.9 ; 2518.84,2356.9 3137.44,2356.9 ; 2518.84,2381.9 3137.44,2381.9 ; 2518.84,2406.9 3137.44,2406.9 ; 2520.84,1206.9 2547.54,1206.9 ; 2539.04,906.9 2539.04,1051.2 ; 2539.04,1188.7 2539.04,1215.5 ; 2539.04,1870 2539.04,1970.9 ; 2539.04,2258.9 2539.04,3046.6 ; 2539.04,3158.8 2539.04,3642.1 ; 2539.04,4007.6 2539.04,4026.1 ; 2539.04,4141.1 2539.04,4152.6 ; 2539.04,4307.6 2539.04,4329.3 ; 2539.04,4444.3 2539.04,4841.9 ; 2544.74,1056.9 2623.34,1056.9 ; 2545.84,1181.9 2572.54,1181.9 ; 2563.14,1306.9 2712.04,1306.9 ; 2563.14,1331.9 2712.04,1331.9 ; 2563.14,1356.9 2712.04,1356.9 ; 2563.14,1381.9 2712.04,1381.9 ; 2563.14,1406.9 2689.54,1406.9 ; 2564.04,906.9 2564.04,1076.2 ; 2564.04,1163.7 2564.04,1190.5 ; 2564.04,1289.5 2564.04,1411.4 ; 2564.04,1870 2564.04,1970.9 ; 2564.04,2258.9 2564.04,3046.6 ; 2564.04,3158.8 2564.04,3642.1 ; 2564.04,4007.6 2564.04,4026.1 ; 2564.04,4141.1 2564.04,4152.6 ; 2564.04,4307.6 2564.04,4329.3 ; 2564.04,4444.3 2564.04,4841.9 ; 2569.74,1081.9 2598.34,1081.9 ; 2570.84,1156.9 2597.24,1156.9 ; 2571.54,1106.9 2596.54,1106.9 ; 2571.54,1131.9 2596.54,1131.9 ; 2571.54,1281.9 2712.04,1281.9 ; 2585.64,1431.9 2689.54,1431.9 ; 2589.04,906.9 2589.04,1165.5 ; 2589.04,1264.5 2589.04,1442.2 ; 2589.04,1882.5 2589.04,1970.9 ; 2589.04,2258.9 2589.04,3046.6 ; 2589.04,3158.8 2589.04,3642.1 ; 2589.04,4007.6 2589.04,4026.1 ; 2589.04,4141.1 2589.04,4152.6 ; 2589.04,4307.6 2589.04,4329.3 ; 2589.04,4444.3 2589.04,4841.9 ; 2596.54,1256.9 2712.04,1256.9 ; 2614.04,906.9 2614.04,1066.2 ; 2614.04,1239.5 2614.04,1442.2 ; 2614.04,1882.5 2614.04,1971 ; 2614.04,2258.9 2614.04,3046.6 ; 2614.04,3158.8 2614.04,3642.1 ; 2614.04,4007.6 2614.04,4026.1 ; 2614.04,4141.1 2614.04,4152.6 ; 2614.04,4307.6 2614.04,4329.3 ; 2614.04,4444.3 2614.04,4841.9 ; 2621.54,1231.9 2722.54,1231.9 ; 2639.04,906.9 2639.04,1041.2 ; 2639.04,1214.5 2639.04,1442.2 ; 2639.04,1882.5 2639.04,1969.8 ; 2639.04,2258.9 2639.04,3046.6 ; 2639.04,3171.3 2639.04,3642.1 ; 2639.04,4007.6 2639.04,4026.1 ; 2639.04,4141.1 2639.04,4152.6 ; 2639.04,4307.6 2639.04,4329.3 ; 2639.04,4444.3 2639.04,4841.9 ; 2646.54,1206.9 2647.24,1206.9 ; 2664.04,906.9 2664.04,1032.4 ; 2664.04,1207.4 2664.04,1442.2 ; 2664.04,1882.5 2664.04,1969.8 ; 2664.04,2258.9 2664.04,3046.6 ; 2664.04,3171.3 2664.04,3642.1 ; 2664.04,4007.6 2664.04,4026.1 ; 2664.04,4141.1 2664.04,4152.6 ; 2664.04,4307.6 2664.04,4329.3 ; 2664.04,4444.3 2664.04,4841.9 ; 2680.54,1881.9 2934.54,1881.9 ; 2682.24,3156.9 2769.64,3156.9 ; 2683.64,2256.9 3154.24,2256.9 ; 2689.04,906.9 2689.04,1032.4 ; 2689.04,1207.4 2689.04,1442.2 ; 2689.04,1868.8 2689.04,1969.8 ; 2689.04,2251.5 2689.04,3046.6 ; 2689.04,3150.1 2689.04,3618.5 ; 2689.04,4007.6 2689.04,4026.1 ; 2689.04,4141.1 2689.04,4152.6 ; 2689.04,4307.6 2689.04,4329.3 ; 2689.04,4444.3 2689.04,4841.9 ; 2695.74,3131.9 2744.64,3131.9 ; 2708.64,2231.9 3129.24,2231.9 ; 2714.04,906.9 2714.04,1032.4 ; 2714.04,1207.4 2714.04,1240.5 ; 2714.04,1868.8 2714.04,1969.8 ; 2714.04,2226.5 2714.04,3046.6 ; 2714.04,3116.6 2714.04,3593.5 ; 2714.04,4141.1 2714.04,4152.6 ; 2714.04,4307.6 2714.04,4329.3 ; 2714.04,4444.3 2714.04,4841.9 ; 2720.84,1206.9 2747.54,1206.9 ; 2733.64,2206.9 3120.74,2206.9 ; 2739.04,906.9 2739.04,1051.2 ; 2739.04,1188.7 2739.04,1215.5 ; 2739.04,1868.8 2739.04,1969.8 ; 2739.04,2201.5 2739.04,3046.6 ; 2739.04,3126.2 2739.04,3584 ; 2739.04,4141.1 2739.04,4152.6 ; 2739.04,4307.6 2739.04,4329.3 ; 2739.04,4444.3 2739.04,4841.9 ; 2744.74,1056.9 2823.34,1056.9 ; 2745.84,1181.9 2772.54,1181.9 ; 2758.64,2181.9 3120.74,2181.9 ; 2764.04,906.9 2764.04,1076.2 ; 2764.04,1163.7 2764.04,1190.5 ; 2764.04,1868.8 2764.04,1969.8 ; 2764.04,2181.3 2764.04,3052.2 ; 2764.04,3151.2 2764.04,3584 ; 2764.04,4141.1 2764.04,4152.6 ; 2764.04,4307.6 2764.04,4329.3 ; 2764.04,4444.3 2764.04,4841.9 ; 2768.64,3056.9 3298.84,3056.9 ; 2769.74,1081.9 2798.34,1081.9 ; 2770.84,1156.9 2797.24,1156.9 ; 2771.54,1106.9 2796.54,1106.9 ; 2771.54,1131.9 2796.54,1131.9 ; 2782.04,1281.9 3376.14,1281.9 ; 2782.04,1306.9 3401.14,1306.9 ; 2782.04,1331.9 3421.14,1331.9 ; 2782.04,1356.9 3421.14,1356.9 ; 2782.04,1381.9 3408.64,1381.9 ; 2789.04,906.9 2789.04,1165.5 ; 2789.04,1264.5 2789.04,1405.9 ; 2789.04,1881.3 2789.04,1969.8 ; 2789.04,2181.3 2789.04,3077.2 ; 2789.04,3176.2 2789.04,3584 ; 2789.04,4141.1 2789.04,4152.6 ; 2789.04,4307.6 2789.04,4329.3 ; 2789.04,4444.3 2789.04,4841.9 ; 2793.64,3081.9 3298.84,3081.9 ; 2796.54,1256.9 3351.14,1256.9 ; 2804.54,1406.9 3169.04,1406.9 ; 2804.54,1431.9 3144.04,1431.9 ; 2814.04,906.9 2814.04,1066.2 ; 2814.04,1239.5 2814.04,1440.2 ; 2814.04,1881.3 2814.04,1969.8 ; 2814.04,2181.3 2814.04,3102.2 ; 2814.04,3201.2 2814.04,3584 ; 2814.04,4141.1 2814.04,4152.6 ; 2814.04,4307.6 2814.04,4329.3 ; 2814.04,4444.3 2814.04,4841.9 ; 2818.64,3106.9 3298.84,3106.9 ; 2821.54,1231.9 3326.14,1231.9 ; 2839.04,906.9 2839.04,1041.2 ; 2839.04,1214.5 2839.04,1440.2 ; 2839.04,1881.3 2839.04,1968.4 ; 2839.04,2181.3 2839.04,3127.2 ; 2839.04,3226.2 2839.04,3584 ; 2839.04,4141.1 2839.04,4152.6 ; 2839.04,4307.6 2839.04,4329.3 ; 2839.04,4444.3 2839.04,4841.9 ; 2843.64,3131.9 3298.84,3131.9 ; 2846.54,1206.9 2847.24,1206.9 ; 2864.04,906.9 2864.04,1032.4 ; 2864.04,1207.4 2864.04,1440.2 ; 2864.04,1712.7 2864.04,1726.3 ; 2864.04,1881.3 2864.04,1968.4 ; 2864.04,2181.3 2864.04,3152.2 ; 2864.04,3251.2 2864.04,3584 ; 2864.04,4141.1 2864.04,4152.6 ; 2864.04,4307.6 2864.04,4329.3 ; 2864.04,4444.3 2864.04,4841.9 ; 2868.64,3156.9 3298.84,3156.9 ; 2869.74,1706.9 2934.54,1706.9 ; 2881.74,1731.9 2934.54,1731.9 ; 2881.74,1756.9 2934.54,1756.9 ; 2881.74,1781.9 2934.54,1781.9 ; 2881.74,1806.9 2934.54,1806.9 ; 2881.74,1831.9 2934.54,1831.9 ; 2881.74,1856.9 2934.54,1856.9 ; 2881.74,2056.9 3120.74,2056.9 ; 2881.74,2081.9 3120.74,2081.9 ; 2881.74,2106.9 3120.74,2106.9 ; 2881.74,2131.9 3120.74,2131.9 ; 2881.74,2156.9 3120.74,2156.9 ; 2889.04,906.9 2889.04,1032.4 ; 2889.04,1207.4 2889.04,1440.2 ; 2889.04,1687.7 2889.04,1968.4 ; 2889.04,2038.4 2889.04,3177.2 ; 2889.04,3276.2 2889.04,3584 ; 2889.04,4141.1 2889.04,4152.6 ; 2889.04,4307.6 2889.04,4329.3 ; 2889.04,4444.3 2889.04,4841.9 ; 2893.64,3181.9 3753.34,3181.9 ; 2894.74,1681.9 2934.54,1681.9 ; 2914.04,906.9 2914.04,1032.4 ; 2914.04,1207.4 2914.04,1440.2 ; 2914.04,1675.2 2914.04,1968.4 ; 2914.04,2038.4 2914.04,3202.2 ; 2914.04,3301.2 2914.04,3584 ; 2914.04,4141.1 2914.04,4152.6 ; 2914.04,4307.6 2914.04,4329.3 ; 2914.04,4444.3 2914.04,4841.9 ; 2918.64,3206.9 3702.34,3206.9 ; 2920.84,1206.9 3237.44,1206.9 ; 2932.24,1456.9 3120.74,1456.9 ; 2932.24,1556.9 2934.54,1556.9 ; 2932.24,1581.9 2934.54,1581.9 ; 2932.24,1606.9 2934.54,1606.9 ; 2932.24,1631.9 2934.54,1631.9 ; 2932.24,1656.9 2934.54,1656.9 ; 2939.04,906.9 2939.04,1051.2 ; 2939.04,1188.7 2939.04,1472.7 ; 2939.04,2038.4 2939.04,3227.2 ; 2939.04,3326.2 2939.04,3584 ; 2939.04,4141.1 2939.04,4152.6 ; 2939.04,4307.6 2939.04,4329.3 ; 2939.04,4444.3 2939.04,4841.9 ; 2943.64,3231.9 3702.34,3231.9 ; 2944.74,1056.9 3227.64,1056.9 ; 2945.84,1181.9 3212.44,1181.9 ; 2959.74,1481.9 3120.74,1481.9 ; 2964.04,906.9 2964.04,1076.2 ; 2964.04,1163.7 2964.04,1486.2 ; 2964.04,2038.4 2964.04,3252.2 ; 2964.04,3351.2 2964.04,3584 ; 2964.04,4141.1 2964.04,4152.6 ; 2964.04,4307.6 2964.04,4329.3 ; 2964.04,4444.3 2964.04,4841.9 ; 2968.64,3256.9 3702.34,3256.9 ; 2969.74,1081.9 3202.64,1081.9 ; 2970.84,1156.9 3193.84,1156.9 ; 2971.54,1106.9 3193.84,1106.9 ; 2971.54,1131.9 3193.84,1131.9 ; 2976.74,2031.9 3120.74,2031.9 ; 2984.74,1506.9 3120.74,1506.9 ; 2989.04,906.9 2989.04,1511.2 ; 2989.04,2019.6 2989.04,3277.2 ; 2989.04,3376.2 2989.04,3584 ; 2989.04,4141.1 2989.04,4152.6 ; 2989.04,4307.6 2989.04,4329.3 ; 2989.04,4444.3 2989.04,4841.9 ; 2993.64,3281.9 3702.34,3281.9 ; 3001.74,2006.9 3120.74,2006.9 ; 3004.54,1531.9 3120.74,1531.9 ; 3004.54,1556.9 3120.74,1556.9 ; 3004.54,1581.9 3120.74,1581.9 ; 3004.54,1606.9 3120.74,1606.9 ; 3004.54,1631.9 3120.74,1631.9 ; 3004.54,1656.9 3120.74,1656.9 ; 3004.54,1681.9 3120.74,1681.9 ; 3004.54,1706.9 3120.74,1706.9 ; 3004.54,1731.9 3120.74,1731.9 ; 3004.54,1756.9 3120.74,1756.9 ; 3004.54,1781.9 3120.74,1781.9 ; 3004.54,1806.9 3120.74,1806.9 ; 3004.54,1831.9 3120.74,1831.9 ; 3004.54,1856.9 3120.74,1856.9 ; 3004.54,1881.9 3120.74,1881.9 ; 3004.54,1906.9 3120.74,1906.9 ; 3004.54,1931.9 3120.74,1931.9 ; 3004.54,1956.9 3120.74,1956.9 ; 3004.54,1981.9 3120.74,1981.9 ; 3014.04,906.9 3014.04,3302.2 ; 3014.04,3401.2 3014.04,3597.5 ; 3014.04,4141.1 3014.04,4152.6 ; 3014.04,4307.6 3014.04,4329.3 ; 3014.04,4444.3 3014.04,4841.9 ; 3018.64,3306.9 3702.34,3306.9 ; 3023.44,3606.9 3094.74,3606.9 ; 3039.04,906.9 3039.04,3327.2 ; 3039.04,3426.2 3039.04,3622.5 ; 3039.04,4141.1 3039.04,4152.6 ; 3039.04,4307.6 3039.04,4329.3 ; 3039.04,4444.3 3039.04,4841.9 ; 3040.74,3631.9 3094.74,3631.9 ; 3040.74,3656.9 3094.74,3656.9 ; 3043.64,3331.9 3714.84,3331.9 ; 3053.24,3681.9 3082.24,3681.9 ; 3053.24,3706.9 3082.24,3706.9 ; 3053.24,3731.9 3065.84,3731.9 ; 3064.04,906.9 3064.04,3352.2 ; 3064.04,3451.2 3064.04,3733.7 ; 3064.04,3832.7 3064.04,3852.6 ; 3064.04,4141.1 3064.04,4152.6 ; 3064.04,4307.6 3064.04,4329.3 ; 3064.04,4444.3 3064.04,4841.9 ; 3064.84,3831.9 3226.04,3831.9 ; 3068.64,3356.9 3714.84,3356.9 ; 3082.14,4156.9 4214.84,4156.9 ; 3082.14,4306.9 4450.24,4306.9 ; 3089.04,906.9 3089.04,3377.2 ; 3089.04,3476.2 3089.04,3660 ; 3089.04,3807.7 3089.04,3852.6 ; 3089.04,4141.1 3089.04,4165.1 ; 3089.04,4295.1 3089.04,4329.3 ; 3089.04,4444.3 3089.04,4841.9 ; 3089.84,3806.9 3251.04,3806.9 ; 3093.64,3381.9 3555.94,3381.9 ; 3114.04,906.9 3114.04,3402.2 ; 3114.04,3782.7 3114.04,3852.6 ; 3114.04,4141.1 3114.04,4165.1 ; 3114.04,4295.1 3114.04,4329.3 ; 3114.04,4444.3 3114.04,4841.9 ; 3114.84,3781.9 3276.04,3781.9 ; 3118.64,3406.9 3530.94,3406.9 ; 3139.04,906.9 3139.04,1436.9 ; 3139.04,2241.7 3139.04,2311.5 ; 3139.04,2446.5 3139.04,3427.2 ; 3139.04,3775 3139.04,3852.6 ; 3139.04,4141.1 3139.04,4165.1 ; 3139.04,4295.1 3139.04,4329.3 ; 3139.04,4444.3 3139.04,4841.9 ; 3143.64,3431.9 3517.14,3431.9 ; 3164.04,906.9 3164.04,1411.9 ; 3164.04,2446.5 3164.04,2529.4 ; 3164.04,2748.2 3164.04,3452.2 ; 3164.04,3775 3164.04,3852.6 ; 3164.04,4141.1 3164.04,4165.1 ; 3164.04,4295.1 3164.04,4329.3 ; 3164.04,4444.3 3164.04,4841.9 ; 3164.74,3456.9 3517.14,3456.9 ; 3164.74,3481.9 3517.14,3481.9 ; 3164.74,3506.9 3517.14,3506.9 ; 3164.74,3531.9 3540.34,3531.9 ; 3164.74,3556.9 3565.34,3556.9 ; 3164.74,3581.9 3714.84,3581.9 ; 3164.74,3606.9 3714.84,3606.9 ; 3164.74,3631.9 3426.04,3631.9 ; 3164.74,3656.9 3401.04,3656.9 ; 3177.24,3681.9 3376.04,3681.9 ; 3177.24,3706.9 3351.04,3706.9 ; 3177.24,3731.9 3326.04,3731.9 ; 3177.24,3756.9 3301.04,3756.9 ; 3182.14,3856.9 3201.04,3856.9 ; 3189.04,906.9 3189.04,1387 ; 3189.04,2446.5 3189.04,2504.4 ; 3189.04,2773.2 3189.04,3868.9 ; 3189.04,4141.1 3189.04,4165.1 ; 3189.04,4295.1 3189.04,4329.3 ; 3189.04,4444.3 3189.04,4841.9 ; 3189.64,4181.9 4214.84,4181.9 ; 3189.64,4206.9 4233.04,4206.9 ; 3189.64,4231.9 4258.04,4231.9 ; 3189.64,4256.9 4450.24,4256.9 ; 3189.64,4281.9 4450.24,4281.9 ; 3214.04,906.9 3214.04,1070.6 ; 3214.04,1183.5 3214.04,1387 ; 3214.04,2446.5 3214.04,2479.4 ; 3214.04,2802.6 3214.04,2822 ; 3214.04,2976.9 3214.04,3843.9 ; 3214.04,4141.1 3214.04,4329.3 ; 3214.04,4444.3 3214.04,4841.9 ; 3239.04,906.9 3239.04,1045.6 ; 3239.04,1208.5 3239.04,1387 ; 3239.04,2446.5 3239.04,2454.4 ; 3239.04,2802.6 3239.04,2822 ; 3239.04,2976.9 3239.04,3818.9 ; 3239.04,4141.1 3239.04,4329.3 ; 3239.04,4444.3 3239.04,4841.9 ; 3264.04,906.9 3264.04,1039.5 ; 3264.04,1214.5 3264.04,1387 ; 3264.04,2802.6 3264.04,2822 ; 3264.04,2976.9 3264.04,3793.9 ; 3264.04,4141.1 3264.04,4329.3 ; 3264.04,4444.3 3264.04,4841.9 ; 3289.04,906.9 3289.04,1039.5 ; 3289.04,1214.5 3289.04,1387 ; 3289.04,2802.6 3289.04,2822 ; 3289.04,2976.9 3289.04,3768.9 ; 3289.04,4133.6 3289.04,4329.3 ; 3289.04,4444.3 3289.04,4841.9 ; 3290.74,4131.9 4182.34,4131.9 ; 3295.34,2756.9 3306.54,2756.9 ; 3295.34,2781.9 3324.34,2781.9 ; 3313.64,4331.9 4450.24,4331.9 ; 3314.04,906.9 3314.04,1039.5 ; 3314.04,1219.8 3314.04,1387 ; 3314.04,2764.4 3314.04,2822 ; 3314.04,2976.9 3314.04,3024 ; 3314.04,3159 3314.04,3743.9 ; 3314.04,4118.6 3314.04,4332.2 ; 3314.04,4441.3 3314.04,4841.9 ; 3323.44,4431.9 4450.24,4431.9 ; 3330.54,2681.9 3565.24,2681.9 ; 3334.94,1056.9 3427.64,1056.9 ; 3338.64,4356.9 4450.24,4356.9 ; 3339.04,906.9 3339.04,1061 ; 3339.04,1244.8 3339.04,1387 ; 3339.04,2677 3339.04,2687.6 ; 3339.04,2802.6 3339.04,2822 ; 3339.04,2976.9 3339.04,3024 ; 3339.04,3159 3339.04,3718.9 ; 3339.04,4118.6 3339.04,4357.2 ; 3339.04,4416.3 3339.04,4841.9 ; 3344.74,4381.9 4450.24,4381.9 ; 3344.74,4406.9 4450.24,4406.9 ; 3359.94,1081.9 3402.64,1081.9 ; 3364.04,906.9 3364.04,1086 ; 3364.04,1269.8 3364.04,1387 ; 3364.04,2677 3364.04,2687.6 ; 3364.04,2802.6 3364.04,2822 ; 3364.04,2976.9 3364.04,3024 ; 3364.04,3159 3364.04,3693.9 ; 3364.04,4118.6 3364.04,4841.9 ; 3368.84,1106.9 3393.84,1106.9 ; 3368.84,1131.9 3393.84,1131.9 ; 3371.34,1156.9 3393.84,1156.9 ; 3389.04,906.9 3389.04,1174.6 ; 3389.04,1294.8 3389.04,1387 ; 3389.04,2677 3389.04,2687.6 ; 3389.04,2802.6 3389.04,2822 ; 3389.04,2976.9 3389.04,3024 ; 3389.04,3159 3389.04,3668.9 ; 3389.04,4118.6 3389.04,4841.9 ; 3396.34,1181.9 3412.44,1181.9 ; 3414.04,906.9 3414.04,1070.6 ; 3414.04,1183.5 3414.04,1199.6 ; 3414.04,1319.8 3414.04,1376.6 ; 3414.04,2677 3414.04,2687.6 ; 3414.04,2802.6 3414.04,2822 ; 3414.04,2976.9 3414.04,3024 ; 3414.04,3159 3414.04,3643.9 ; 3414.04,4118.6 3414.04,4841.9 ; 3419.34,2706.9 3565.24,2706.9 ; 3419.34,2731.9 3565.24,2731.9 ; 3419.34,2756.9 3582.14,2756.9 ; 3419.34,2781.9 3605.84,2781.9 ; 3421.34,1206.9 3437.44,1206.9 ; 3423.84,2831.9 3605.74,2831.9 ; 3439.04,906.9 3439.04,1045.6 ; 3439.04,1208.5 3439.04,1224.6 ; 3439.04,2677 3439.04,2834.5 ; 3439.04,3159 3439.04,3623.4 ; 3439.04,4118.6 3439.04,4841.9 ; 3446.34,1231.9 3526.04,1231.9 ; 3464.04,906.9 3464.04,1039.5 ; 3464.04,1214.5 3464.04,1249.6 ; 3464.04,2677 3464.04,2834.5 ; 3464.04,3159 3464.04,3623.4 ; 3464.04,4118.6 3464.04,4841.9 ; 3471.34,1256.9 3551.04,1256.9 ; 3489.04,906.9 3489.04,1039.5 ; 3489.04,1214.5 3489.04,1274.6 ; 3489.04,2677 3489.04,2834.5 ; 3489.04,3159 3489.04,3623.4 ; 3489.04,4118.6 3489.04,4841.9 ; 3496.34,1281.9 3574.64,1281.9 ; 3501.34,2506.9 3525.84,2506.9 ; 3501.34,2981.9 3828.24,2981.9 ; 3501.34,3006.9 3828.24,3006.9 ; 3506.14,1306.9 3574.64,1306.9 ; 3506.14,1331.9 3574.64,1331.9 ; 3506.14,1356.9 3574.64,1356.9 ; 3514.04,906.9 3514.04,1039.5 ; 3514.04,1219.9 3514.04,1377.3 ; 3514.04,2495.1 3514.04,2522 ; 3514.04,2677 3514.04,2834.5 ; 3514.04,2964.4 3514.04,3024 ; 3514.04,3159 3514.04,3623.4 ; 3514.04,4118.6 3514.04,4841.9 ; 3518.64,1381.9 3562.14,1381.9 ; 3523.84,2531.9 3565.24,2531.9 ; 3523.84,2556.9 3565.24,2556.9 ; 3523.84,2581.9 3565.24,2581.9 ; 3523.84,2606.9 3565.24,2606.9 ; 3523.84,2631.9 3565.24,2631.9 ; 3523.84,2656.9 3565.24,2656.9 ; 3531.34,2856.9 3605.74,2856.9 ; 3531.34,2881.9 3605.74,2881.9 ; 3531.34,2906.9 3605.74,2906.9 ; 3531.34,2931.9 3605.74,2931.9 ; 3531.34,2956.9 3605.74,2956.9 ; 3533.84,3031.9 3696.44,3031.9 ; 3533.84,3056.9 3696.44,3056.9 ; 3533.84,3081.9 3696.44,3081.9 ; 3533.84,3106.9 3696.44,3106.9 ; 3533.84,3131.9 3696.44,3131.9 ; 3533.84,3156.9 3696.44,3156.9 ; 3534.94,1056.9 3627.64,1056.9 ; 3536.14,1406.9 3544.64,1406.9 ; 3536.14,1431.9 3544.64,1431.9 ; 3539.04,906.9 3539.04,1061 ; 3539.04,1244.9 3539.04,1447.5 ; 3539.04,2520.1 3539.04,3398.8 ; 3539.04,3530.6 3539.04,3623.4 ; 3539.04,4118.6 3539.04,4638.2 ; 3539.04,4769.9 3539.04,4841.9 ; 3559.94,1081.9 3602.64,1081.9 ; 3564.04,906.9 3564.04,1086 ; 3564.04,1269.9 3564.04,1380 ; 3564.04,2521.3 3564.04,3373.8 ; 3564.04,3555.6 3564.04,3623.4 ; 3564.04,4118.6 3564.04,4613.2 ; 3564.04,4794.9 3564.04,4841.9 ; 3568.84,1106.9 3593.84,1106.9 ; 3568.84,1131.9 3593.84,1131.9 ; 3571.24,1156.9 3593.84,1156.9 ; 3587.54,1531.9 3745.34,1531.9 ; 3587.54,1556.9 3763.04,1556.9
